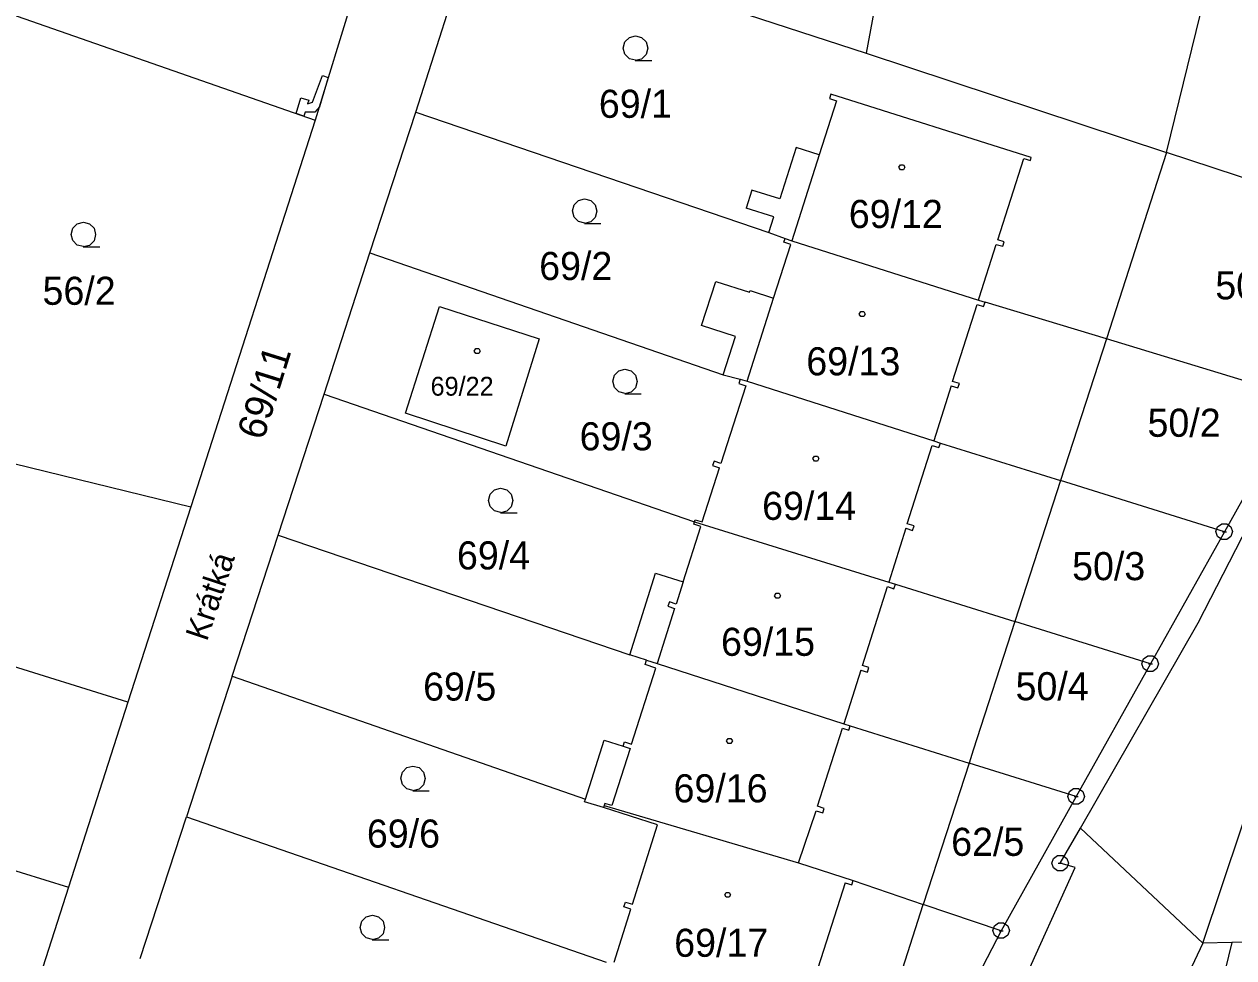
# Model space of a CAD drawing. Extents: x -759060 to -757386, y -1172273 to -1170948.
# Drawn here: x -757948.7 to -757875.5, y -1171352.6 to -1171296.1 of the extents above; entities that cross this region are included whole.
import ezdxf

# ---------------------------------------------------------------- set-up
doc = ezdxf.new("R2010")
doc.units = 0
for name, color, linetype in [('Vrstva 1', 7, 'Continuous'), ('Vrstva 12', 7, 'Continuous'), ('Vrstva 13', 7, 'Continuous'), ('Vrstva 2', 7, 'Continuous'), ('Vrstva 3', 7, 'Continuous'), ('Vrstva 4', 7, 'Continuous'), ('Vrstva 5', 7, 'Continuous'), ('Vrstva 7', 7, 'Continuous'), ('Vrstva 8', 7, 'Continuous')]:
    doc.layers.add(name, color=color, linetype=linetype)

msp = doc.modelspace()

# ---------------------------------------------------------------- linework, layer by layer
at = {"layer": 'Vrstva 1'}
for p, q in [((-757892.1, -1171267.11), (-757897.76, -1171297.84)), ((-757879.58, -1171303.85), (-757871.52, -1171270.95)), ((-757925.59, -1171283.81), (-757931.1, -1171301.9)), ((-757925.02, -1171301.41), (-757921.41, -1171290.12)), ((-757921.41, -1171290.12), (-757897.76, -1171297.84)), ((-757950, -1171295.3), (-757931.1, -1171301.9)), ((-757897.76, -1171297.84), (-757879.58, -1171303.85)), ((-757899.89, -1171300.32), (-757899.97, -1171300.59)), ((-757887.77, -1171304.16), (-757899.89, -1171300.32)), ((-757899.55, -1171300.73), (-757900.6, -1171303.99)), ((-757899.97, -1171300.59), (-757899.55, -1171300.73)), ((-757931.1, -1171301.9), (-757938.63, -1171325.3)), ((-757927.79, -1171309.92), (-757925.02, -1171301.41)), ((-757925.02, -1171301.41), (-757903.64, -1171308.7)), ((-757902, -1171303.54), (-757902.99, -1171306.66)), ((-757900.6, -1171303.99), (-757902, -1171303.54)), ((-757879.58, -1171303.85), (-757883.22, -1171315.14)), ((-757867.49, -1171307.82), (-757879.58, -1171303.85)), ((-757889.8, -1171309.14), (-757888.22, -1171304.21)), ((-757888.22, -1171304.21), (-757887.82, -1171304.34)), ((-757887.82, -1171304.34), (-757887.77, -1171304.16)), ((-757904.68, -1171306.12), (-757905.03, -1171307.22)), ((-757902.99, -1171306.66), (-757904.68, -1171306.12)), ((-757903.34, -1171307.75), (-757905.03, -1171307.22)), ((-757903.64, -1171308.7), (-757903.34, -1171307.75)), ((-757877.67, -1171332.33), (-757865.47, -1171308.48)), ((-757903.64, -1171308.7), (-757902.67, -1171309.05)), ((-757902.74, -1171309.28), (-757902.67, -1171309.05)), ((-757902.32, -1171309.41), (-757902.74, -1171309.28)), ((-757902.67, -1171309.05), (-757902.25, -1171309.19)), ((-757902.25, -1171309.19), (-757890.97, -1171312.79)), ((-757889.4, -1171309.26), (-757889.8, -1171309.14)), ((-757889.49, -1171309.53), (-757889.4, -1171309.26)), ((-757930.57, -1171318.47), (-757927.79, -1171309.92)), ((-757927.79, -1171309.92), (-757906.41, -1171317.31)), ((-757903.36, -1171312.66), (-757902.32, -1171309.41)), ((-757890.92, -1171312.65), (-757889.89, -1171309.41)), ((-757889.89, -1171309.41), (-757889.49, -1171309.53)), ((-757907.72, -1171314.32), (-757906.86, -1171311.66)), ((-757906.86, -1171311.66), (-757904.82, -1171312.31)), ((-757904.82, -1171312.31), (-757904.77, -1171312.2)), ((-757904.77, -1171312.2), (-757903.36, -1171312.66)), ((-757890.97, -1171312.79), (-757890.92, -1171312.65)), ((-757890.97, -1171312.79), (-757890.56, -1171312.92)), ((-757883.22, -1171315.14), (-757890.56, -1171312.92)), ((-757925.64, -1171319.63), (-757923.58, -1171313.18)), ((-757923.58, -1171313.18), (-757917.55, -1171315.13)), ((-757905.67, -1171314.98), (-757907.72, -1171314.32)), ((-757917.55, -1171315.13), (-757919.57, -1171321.62)), ((-757906.41, -1171317.31), (-757905.67, -1171314.98)), ((-757883.22, -1171315.14), (-757886, -1171323.71)), ((-757871.53, -1171318.68), (-757883.22, -1171315.14)), ((-757906.41, -1171317.31), (-757905.38, -1171317.57)), ((-757905.05, -1171317.97), (-757906.55, -1171322.67)), ((-757905.38, -1171317.57), (-757905.47, -1171317.84)), ((-757905.47, -1171317.84), (-757905.05, -1171317.97)), ((-757905.38, -1171317.57), (-757904.96, -1171317.7)), ((-757904.96, -1171317.7), (-757893.67, -1171321.31)), ((-757933.35, -1171327.02), (-757930.57, -1171318.47)), ((-757930.57, -1171318.47), (-757908.14, -1171326.21)), ((-757871.53, -1171318.68), (-757876.08, -1171326.81)), ((-757919.57, -1171321.62), (-757925.64, -1171319.63)), ((-757958.04, -1171320.56), (-757938.63, -1171325.3)), ((-757893.67, -1171321.31), (-757893.27, -1171321.44)), ((-757893.27, -1171321.44), (-757886, -1171323.71)), ((-757907.68, -1171326.21), (-757906.63, -1171322.94)), ((-757906.96, -1171322.54), (-757907.05, -1171322.8)), ((-757907.05, -1171322.8), (-757906.63, -1171322.94)), ((-757906.55, -1171322.67), (-757906.96, -1171322.54)), ((-757886, -1171323.71), (-757888.76, -1171332.25)), ((-757876.08, -1171326.81), (-757886, -1171323.71)), ((-757942.44, -1171337.12), (-757982.63, -1171324.67)), ((-757938.63, -1171325.3), (-757942.44, -1171337.12)), ((-757908.14, -1171326.21), (-757908.1, -1171326.08)), ((-757908.1, -1171326.08), (-757907.68, -1171326.21)), ((-757908.83, -1171329.84), (-757907.76, -1171326.49)), ((-757908.18, -1171326.35), (-757908.14, -1171326.21)), ((-757907.76, -1171326.49), (-757908.18, -1171326.35)), ((-757908.14, -1171326.21), (-757896.39, -1171329.86)), ((-757876.08, -1171326.81), (-757880.56, -1171334.81)), ((-757936.13, -1171335.56), (-757933.35, -1171327.02)), ((-757933.35, -1171327.02), (-757912.07, -1171334.26)), ((-757912.07, -1171334.26), (-757910.5, -1171329.31)), ((-757910.5, -1171329.31), (-757908.83, -1171329.84)), ((-757896.39, -1171329.86), (-757895.99, -1171329.99)), ((-757895.99, -1171329.99), (-757888.76, -1171332.25)), ((-757888.76, -1171332.25), (-757891.28, -1171340.03)), ((-757880.56, -1171334.81), (-757888.76, -1171332.25)), ((-757884.79, -1171344.75), (-757877.67, -1171332.33)), ((-757911.05, -1171334.59), (-757912.07, -1171334.26)), ((-757911.14, -1171334.85), (-757911.05, -1171334.59)), ((-757910.49, -1171335.06), (-757911.14, -1171334.85)), ((-757911.05, -1171334.59), (-757910.41, -1171334.79)), ((-757910.41, -1171334.79), (-757899.11, -1171338.44)), ((-757880.56, -1171334.81), (-757885.05, -1171342.84)), ((-757936.13, -1171335.56), (-757938.9, -1171344.07)), ((-757936.13, -1171335.56), (-757914.75, -1171342.99)), ((-757911.96, -1171339.66), (-757910.49, -1171335.06)), ((-757984.73, -1171336.38), (-757946.04, -1171348.32)), ((-757942.44, -1171337.12), (-757946.04, -1171348.32)), ((-757899.11, -1171338.44), (-757898.72, -1171338.56)), ((-757898.72, -1171338.56), (-757891.53, -1171340.81)), ((-757877.39, -1171351.72), (-757872.81, -1171338.04)), ((-757914.75, -1171342.99), (-757913.62, -1171339.43)), ((-757913.62, -1171339.43), (-757912.47, -1171339.79)), ((-757912.47, -1171339.79), (-757912.38, -1171339.53)), ((-757912.38, -1171339.53), (-757911.96, -1171339.66)), ((-757891.28, -1171340.03), (-757891.53, -1171340.81)), ((-757891.53, -1171340.81), (-757894.3, -1171349.37)), ((-757885.05, -1171342.84), (-757891.53, -1171340.81)), ((-757885.05, -1171342.84), (-757889.59, -1171350.96)), ((-757914.8, -1171343.15), (-757914.75, -1171342.99)), ((-757913.66, -1171343.51), (-757914.8, -1171343.15)), ((-757913.61, -1171343.39), (-757913.66, -1171343.51)), ((-757910.38, -1171344.56), (-757913.66, -1171343.51)), ((-757913.61, -1171343.39), (-757901.85, -1171346.86)), ((-757941.69, -1171352.64), (-757938.9, -1171344.07)), ((-757938.9, -1171344.07), (-757913.49, -1171352.86)), ((-757911.91, -1171349.36), (-757910.38, -1171344.56)), ((-757886.01, -1171346.88), (-757884.79, -1171344.75)), ((-757877.39, -1171351.72), (-757884.79, -1171344.75)), ((-757904.22, -1171389.43), (-757885.12, -1171347.13)), ((-757901.85, -1171346.86), (-757898.55, -1171347.93)), ((-757885.12, -1171347.13), (-757886.01, -1171346.88)), ((-757898.55, -1171347.93), (-757894.3, -1171349.37)), ((-757946.04, -1171348.32), (-757949.39, -1171358.74)), ((-757912.42, -1171349.51), (-757912.33, -1171349.23)), ((-757912, -1171349.65), (-757912.42, -1171349.51)), ((-757912.33, -1171349.23), (-757911.91, -1171349.36)), ((-757897.07, -1171357.94), (-757894.3, -1171349.37)), ((-757889.59, -1171350.96), (-757894.3, -1171349.37)), ((-757913.02, -1171352.86), (-757912, -1171349.65)), ((-757889.59, -1171350.96), (-757893.43, -1171358.41)), ((-757877.39, -1171351.72), (-757898.83, -1171397.44)), ((-757875.62, -1171351.68), (-757877.39, -1171351.72)), ((-757875.62, -1171351.68), (-757876.99, -1171357.1)), ((-757869.76, -1171351.53), (-757875.62, -1171351.68))]:
    msp.add_line(p, q, dxfattribs=at)
at = {"layer": 'Vrstva 12'}
for p, q in [((-757899.89, -1171300.32), (-757899.97, -1171300.59)), ((-757887.77, -1171304.16), (-757899.89, -1171300.32)), ((-757899.55, -1171300.73), (-757900.6, -1171303.99)), ((-757899.97, -1171300.59), (-757899.55, -1171300.73)), ((-757900.6, -1171303.99), (-757902.25, -1171309.19)), ((-757889.8, -1171309.14), (-757888.22, -1171304.21)), ((-757888.22, -1171304.21), (-757887.82, -1171304.34)), ((-757887.82, -1171304.34), (-757887.77, -1171304.16)), ((-757902.74, -1171309.28), (-757902.67, -1171309.05)), ((-757902.32, -1171309.41), (-757902.74, -1171309.28)), ((-757902.67, -1171309.05), (-757902.25, -1171309.19)), ((-757902.25, -1171309.19), (-757890.97, -1171312.79)), ((-757902.25, -1171309.19), (-757890.97, -1171312.79)), ((-757889.4, -1171309.26), (-757889.8, -1171309.14)), ((-757889.49, -1171309.53), (-757889.4, -1171309.26)), ((-757903.36, -1171312.66), (-757902.32, -1171309.41)), ((-757890.92, -1171312.65), (-757889.89, -1171309.41)), ((-757889.89, -1171309.41), (-757889.49, -1171309.53)), ((-757904.96, -1171317.7), (-757903.36, -1171312.66)), ((-757890.97, -1171312.79), (-757890.92, -1171312.65)), ((-757890.97, -1171312.79), (-757890.56, -1171312.92)), ((-757890.65, -1171313.18), (-757890.56, -1171312.92)), ((-757925.64, -1171319.63), (-757923.58, -1171313.18)), ((-757923.58, -1171313.18), (-757917.55, -1171315.13)), ((-757892.53, -1171317.71), (-757891.05, -1171313.06)), ((-757891.05, -1171313.06), (-757890.65, -1171313.18)), ((-757917.55, -1171315.13), (-757919.57, -1171321.62)), ((-757905.05, -1171317.97), (-757906.55, -1171322.67)), ((-757905.38, -1171317.57), (-757905.47, -1171317.84)), ((-757905.47, -1171317.84), (-757905.05, -1171317.97)), ((-757905.38, -1171317.57), (-757904.96, -1171317.7)), ((-757904.96, -1171317.7), (-757893.67, -1171321.31)), ((-757904.96, -1171317.7), (-757893.67, -1171321.31)), ((-757892.61, -1171317.97), (-757893.67, -1171321.31)), ((-757892.61, -1171317.97), (-757892.22, -1171318.1)), ((-757892.12, -1171317.84), (-757892.53, -1171317.71)), ((-757892.22, -1171318.1), (-757892.12, -1171317.84)), ((-757919.57, -1171321.62), (-757925.64, -1171319.63)), ((-757895.27, -1171326.33), (-757893.76, -1171321.58)), ((-757893.76, -1171321.58), (-757893.36, -1171321.71)), ((-757893.67, -1171321.31), (-757893.27, -1171321.44)), ((-757893.36, -1171321.71), (-757893.27, -1171321.44)), ((-757907.68, -1171326.21), (-757906.63, -1171322.94)), ((-757906.96, -1171322.54), (-757907.05, -1171322.8)), ((-757907.05, -1171322.8), (-757906.63, -1171322.94)), ((-757906.55, -1171322.67), (-757906.96, -1171322.54)), ((-757908.14, -1171326.21), (-757908.1, -1171326.08)), ((-757908.1, -1171326.08), (-757907.68, -1171326.21)), ((-757908.83, -1171329.84), (-757907.76, -1171326.49)), ((-757908.18, -1171326.35), (-757908.14, -1171326.21)), ((-757907.76, -1171326.49), (-757908.18, -1171326.35)), ((-757908.14, -1171326.21), (-757896.39, -1171329.86)), ((-757908.14, -1171326.21), (-757896.39, -1171329.86)), ((-757895.36, -1171326.6), (-757896.39, -1171329.86)), ((-757895.36, -1171326.6), (-757894.95, -1171326.73)), ((-757894.86, -1171326.46), (-757895.27, -1171326.33)), ((-757894.95, -1171326.73), (-757894.86, -1171326.46)), ((-757908.83, -1171329.84), (-757909.26, -1171331.19)), ((-757897.99, -1171334.9), (-757896.47, -1171330.13)), ((-757896.47, -1171330.13), (-757896.08, -1171330.26)), ((-757896.39, -1171329.86), (-757895.99, -1171329.99)), ((-757896.08, -1171330.26), (-757895.99, -1171329.99)), ((-757909.67, -1171331.05), (-757909.76, -1171331.32)), ((-757909.26, -1171331.19), (-757909.67, -1171331.05)), ((-757909.35, -1171331.45), (-757910.41, -1171334.79)), ((-757909.76, -1171331.32), (-757909.35, -1171331.45)), ((-757911.14, -1171334.85), (-757911.05, -1171334.59)), ((-757910.49, -1171335.06), (-757911.14, -1171334.85)), ((-757911.05, -1171334.59), (-757910.41, -1171334.79)), ((-757910.41, -1171334.79), (-757899.11, -1171338.44)), ((-757910.41, -1171334.79), (-757899.11, -1171338.44)), ((-757897.59, -1171335.03), (-757897.99, -1171334.9)), ((-757911.96, -1171339.66), (-757910.49, -1171335.06)), ((-757898.08, -1171335.18), (-757899.11, -1171338.44)), ((-757898.08, -1171335.18), (-757897.68, -1171335.3)), ((-757897.68, -1171335.3), (-757897.59, -1171335.03)), ((-757899.11, -1171338.44), (-757898.72, -1171338.56)), ((-757898.8, -1171338.83), (-757898.72, -1171338.56)), ((-757900.71, -1171343.43), (-757899.2, -1171338.7)), ((-757899.2, -1171338.7), (-757898.8, -1171338.83)), ((-757912.05, -1171339.93), (-757913.15, -1171343.39)), ((-757912.47, -1171339.79), (-757912.38, -1171339.53)), ((-757912.47, -1171339.79), (-757912.05, -1171339.93)), ((-757912.38, -1171339.53), (-757911.96, -1171339.66)), ((-757913.61, -1171343.39), (-757913.66, -1171343.51)), ((-757910.38, -1171344.56), (-757913.66, -1171343.51)), ((-757913.57, -1171343.26), (-757913.61, -1171343.39)), ((-757913.61, -1171343.39), (-757901.85, -1171346.86)), ((-757913.61, -1171343.39), (-757901.85, -1171346.86)), ((-757913.15, -1171343.39), (-757913.57, -1171343.26)), ((-757900.3, -1171343.56), (-757900.71, -1171343.43)), ((-757900.39, -1171343.83), (-757900.3, -1171343.56)), ((-757901.85, -1171346.86), (-757900.79, -1171343.7)), ((-757900.79, -1171343.7), (-757900.39, -1171343.83)), ((-757911.91, -1171349.36), (-757910.38, -1171344.56)), ((-757901.85, -1171346.86), (-757898.55, -1171347.93)), ((-757899.03, -1171348.06), (-757901.72, -1171356.43)), ((-757899.03, -1171348.06), (-757898.63, -1171348.19)), ((-757898.63, -1171348.19), (-757898.55, -1171347.93)), ((-757912.42, -1171349.51), (-757912.33, -1171349.23)), ((-757912, -1171349.65), (-757912.42, -1171349.51)), ((-757912.33, -1171349.23), (-757911.91, -1171349.36)), ((-757913.02, -1171352.86), (-757912, -1171349.65))]:
    msp.add_line(p, q, dxfattribs=at)
at = {"layer": 'Vrstva 13'}
for p, q in [((-757931.27, -1171300.8), (-757930.66, -1171299.18)), ((-757930.31, -1171299.31), (-757930.85, -1171301.08)), ((-757930.66, -1171299.18), (-757930.31, -1171299.31)), ((-757932.26, -1171301.49), (-757931.97, -1171300.54)), ((-757931.97, -1171300.54), (-757931.49, -1171300.68)), ((-757931.49, -1171300.68), (-757931.56, -1171300.91)), ((-757931.56, -1171300.91), (-757931.27, -1171300.8)), ((-757930.85, -1171301.08), (-757931.12, -1171301.41)), ((-757931.79, -1171301.66), (-757932.26, -1171301.49)), ((-757931.72, -1171301.41), (-757931.79, -1171301.66)), ((-757931.12, -1171301.41), (-757931.72, -1171301.41))]:
    msp.add_line(p, q, dxfattribs=at)
at = {"layer": 'Vrstva 3'}
for points in [[(-757911.71, -1171298.27), (-757912.09, -1171298.17), (-757912.36, -1171297.9), (-757912.46, -1171297.53), (-757912.36, -1171297.16), (-757912.09, -1171296.89), (-757911.72, -1171296.79), (-757911.35, -1171296.89), (-757911.08, -1171297.16), (-757910.98, -1171297.54), (-757911.08, -1171297.92), (-757911.35, -1171298.19), (-757911.73, -1171298.29), (-757910.73, -1171298.29)], [(-757914.79, -1171308.13), (-757915.17, -1171308.03), (-757915.44, -1171307.76), (-757915.54, -1171307.39), (-757915.44, -1171307.02), (-757915.17, -1171306.75), (-757914.8, -1171306.65), (-757914.43, -1171306.75), (-757914.16, -1171307.02), (-757914.06, -1171307.4), (-757914.16, -1171307.78), (-757914.43, -1171308.05), (-757914.81, -1171308.15), (-757913.81, -1171308.15)], [(-757945.12, -1171309.55), (-757945.5, -1171309.45), (-757945.77, -1171309.18), (-757945.87, -1171308.81), (-757945.77, -1171308.44), (-757945.5, -1171308.17), (-757945.13, -1171308.07), (-757944.76, -1171308.17), (-757944.49, -1171308.44), (-757944.39, -1171308.82), (-757944.49, -1171309.2), (-757944.76, -1171309.47), (-757945.14, -1171309.57), (-757944.14, -1171309.57)], [(-757912.35, -1171318.44), (-757912.73, -1171318.34), (-757913, -1171318.07), (-757913.1, -1171317.7), (-757913, -1171317.33), (-757912.73, -1171317.06), (-757912.36, -1171316.96), (-757911.99, -1171317.06), (-757911.72, -1171317.33), (-757911.62, -1171317.71), (-757911.72, -1171318.09), (-757911.99, -1171318.36), (-757912.37, -1171318.46), (-757911.37, -1171318.46)], [(-757919.87, -1171325.65), (-757920.25, -1171325.55), (-757920.52, -1171325.28), (-757920.62, -1171324.91), (-757920.52, -1171324.54), (-757920.25, -1171324.27), (-757919.88, -1171324.17), (-757919.51, -1171324.27), (-757919.24, -1171324.54), (-757919.14, -1171324.92), (-757919.24, -1171325.3), (-757919.51, -1171325.57), (-757919.89, -1171325.67), (-757918.89, -1171325.67)], [(-757925.18, -1171342.47), (-757925.56, -1171342.37), (-757925.83, -1171342.1), (-757925.93, -1171341.73), (-757925.83, -1171341.36), (-757925.56, -1171341.09), (-757925.19, -1171340.99), (-757924.82, -1171341.09), (-757924.55, -1171341.36), (-757924.45, -1171341.74), (-757924.55, -1171342.12), (-757924.82, -1171342.39), (-757925.2, -1171342.49), (-757924.2, -1171342.49)], [(-757927.63, -1171351.5), (-757928.01, -1171351.4), (-757928.28, -1171351.13), (-757928.38, -1171350.76), (-757928.28, -1171350.39), (-757928.01, -1171350.12), (-757927.64, -1171350.02), (-757927.27, -1171350.12), (-757927, -1171350.39), (-757926.9, -1171350.77), (-757927, -1171351.15), (-757927.27, -1171351.42), (-757927.65, -1171351.52), (-757926.65, -1171351.52)]]:
    msp.add_lwpolyline(points, dxfattribs=at)
at = {"layer": 'Vrstva 4'}
for p, q in [((-757900.6, -1171303.99), (-757902.25, -1171309.19)), ((-757904.96, -1171317.7), (-757903.36, -1171312.66)), ((-757890.65, -1171313.18), (-757890.56, -1171312.92)), ((-757892.53, -1171317.71), (-757891.05, -1171313.06)), ((-757891.05, -1171313.06), (-757890.65, -1171313.18)), ((-757892.61, -1171317.97), (-757893.67, -1171321.31)), ((-757892.61, -1171317.97), (-757892.22, -1171318.1)), ((-757892.12, -1171317.84), (-757892.53, -1171317.71)), ((-757892.22, -1171318.1), (-757892.12, -1171317.84)), ((-757895.27, -1171326.33), (-757893.76, -1171321.58)), ((-757893.76, -1171321.58), (-757893.36, -1171321.71)), ((-757893.36, -1171321.71), (-757893.27, -1171321.44)), ((-757895.36, -1171326.6), (-757896.39, -1171329.86)), ((-757895.36, -1171326.6), (-757894.95, -1171326.73)), ((-757894.86, -1171326.46), (-757895.27, -1171326.33)), ((-757894.95, -1171326.73), (-757894.86, -1171326.46)), ((-757908.83, -1171329.84), (-757909.26, -1171331.19)), ((-757897.99, -1171334.9), (-757896.47, -1171330.13)), ((-757896.47, -1171330.13), (-757896.08, -1171330.26)), ((-757896.08, -1171330.26), (-757895.99, -1171329.99)), ((-757909.67, -1171331.05), (-757909.76, -1171331.32)), ((-757909.26, -1171331.19), (-757909.67, -1171331.05)), ((-757909.35, -1171331.45), (-757910.41, -1171334.79)), ((-757909.76, -1171331.32), (-757909.35, -1171331.45)), ((-757897.59, -1171335.03), (-757897.99, -1171334.9)), ((-757898.08, -1171335.18), (-757899.11, -1171338.44)), ((-757898.08, -1171335.18), (-757897.68, -1171335.3)), ((-757897.68, -1171335.3), (-757897.59, -1171335.03)), ((-757898.8, -1171338.83), (-757898.72, -1171338.56)), ((-757900.71, -1171343.43), (-757899.2, -1171338.7)), ((-757899.2, -1171338.7), (-757898.8, -1171338.83)), ((-757912.05, -1171339.93), (-757913.15, -1171343.39)), ((-757912.47, -1171339.79), (-757912.05, -1171339.93)), ((-757913.57, -1171343.26), (-757913.61, -1171343.39)), ((-757913.15, -1171343.39), (-757913.57, -1171343.26)), ((-757900.3, -1171343.56), (-757900.71, -1171343.43)), ((-757900.39, -1171343.83), (-757900.3, -1171343.56)), ((-757901.85, -1171346.86), (-757900.79, -1171343.7)), ((-757900.79, -1171343.7), (-757900.39, -1171343.83)), ((-757899.03, -1171348.06), (-757901.72, -1171356.43)), ((-757899.03, -1171348.06), (-757898.63, -1171348.19)), ((-757898.63, -1171348.19), (-757898.55, -1171347.93))]:
    msp.add_line(p, q, dxfattribs=at)
at = {"layer": 'Vrstva 5'}
for points in [[(-757895.51, -1171304.59), (-757895.42, -1171304.74), (-757895.51, -1171304.89), (-757895.69, -1171304.89), (-757895.78, -1171304.74), (-757895.69, -1171304.59)], [(-757897.91, -1171313.48), (-757897.82, -1171313.63), (-757897.91, -1171313.78), (-757898.09, -1171313.78), (-757898.18, -1171313.63), (-757898.09, -1171313.48)], [(-757921.21, -1171315.72), (-757921.12, -1171315.87), (-757921.21, -1171316.02), (-757921.39, -1171316.02), (-757921.48, -1171315.87), (-757921.39, -1171315.72)], [(-757900.71, -1171322.23), (-757900.62, -1171322.38), (-757900.71, -1171322.53), (-757900.89, -1171322.53), (-757900.98, -1171322.38), (-757900.89, -1171322.23)], [(-757903.03, -1171330.53), (-757902.94, -1171330.68), (-757903.03, -1171330.83), (-757903.21, -1171330.83), (-757903.3, -1171330.68), (-757903.21, -1171330.53)], [(-757905.94, -1171339.32), (-757905.85, -1171339.47), (-757905.94, -1171339.62), (-757906.12, -1171339.62), (-757906.21, -1171339.47), (-757906.12, -1171339.32)], [(-757906.05, -1171348.64), (-757905.96, -1171348.79), (-757906.05, -1171348.94), (-757906.23, -1171348.94), (-757906.32, -1171348.79), (-757906.23, -1171348.64)]]:
    msp.add_lwpolyline(points, close=True, dxfattribs=at)
at = {"layer": 'Vrstva 8'}
for p, q in [((-757876.2, -1171326.81), (-757875.96, -1171326.81)), ((-757880.68, -1171334.81), (-757880.44, -1171334.81)), ((-757885.17, -1171342.84), (-757884.93, -1171342.84)), ((-757886.13, -1171346.88), (-757885.89, -1171346.88)), ((-757889.71, -1171350.96), (-757889.47, -1171350.96))]:
    msp.add_line(p, q, dxfattribs=at)
for points in [[(-757875.93, -1171326.33), (-757875.68, -1171326.51), (-757875.58, -1171326.8), (-757875.68, -1171327.09), (-757875.93, -1171327.27), (-757876.24, -1171327.27), (-757876.49, -1171327.09), (-757876.59, -1171326.8), (-757876.49, -1171326.51), (-757876.24, -1171326.33)], [(-757880.41, -1171334.33), (-757880.16, -1171334.51), (-757880.06, -1171334.8), (-757880.16, -1171335.09), (-757880.41, -1171335.27), (-757880.72, -1171335.27), (-757880.97, -1171335.09), (-757881.07, -1171334.8), (-757880.97, -1171334.51), (-757880.72, -1171334.33)], [(-757884.9, -1171342.36), (-757884.65, -1171342.54), (-757884.55, -1171342.83), (-757884.65, -1171343.12), (-757884.9, -1171343.3), (-757885.21, -1171343.3), (-757885.46, -1171343.12), (-757885.56, -1171342.83), (-757885.46, -1171342.54), (-757885.21, -1171342.36)], [(-757885.86, -1171346.4), (-757885.61, -1171346.58), (-757885.51, -1171346.87), (-757885.61, -1171347.16), (-757885.86, -1171347.34), (-757886.17, -1171347.34), (-757886.42, -1171347.16), (-757886.52, -1171346.87), (-757886.42, -1171346.58), (-757886.17, -1171346.4)], [(-757889.44, -1171350.48), (-757889.19, -1171350.66), (-757889.09, -1171350.95), (-757889.19, -1171351.24), (-757889.44, -1171351.42), (-757889.75, -1171351.42), (-757890, -1171351.24), (-757890.1, -1171350.95), (-757890, -1171350.66), (-757889.75, -1171350.48)]]:
    msp.add_lwpolyline(points, close=True, dxfattribs=at)

# ---------------------------------------------------------------- texts
at = {"layer": 'Vrstva 2'}
for s, height, p in [('69/1', 1.7, (-757913.936, -1171301.75)), ('69/12', 1.7, (-757898.809, -1171308.42)), ('69/2', 1.7, (-757917.547, -1171311.57)), ('56/2', 1.7, (-757947.604, -1171313.07)), ('50/1', 1.7, (-757876.629, -1171312.74)), ('69/13', 1.7, (-757901.382, -1171317.34)), ('69/22', 1.14, (-757924.121, -1171318.57)), ('50/2', 1.7, (-757880.731, -1171321.06)), ('69/3', 1.7, (-757915.101, -1171321.88)), ('69/14', 1.7, (-757904.055, -1171326.09)), ('69/4', 1.7, (-757922.524, -1171329.09)), ('50/3', 1.7, (-757885.295, -1171329.74)), ('69/15', 1.7, (-757906.542, -1171334.32)), ('69/5', 1.7, (-757924.571, -1171337.03)), ('50/4', 1.7, (-757888.717, -1171337.01)), ('69/16', 1.7, (-757909.415, -1171343.19)), ('69/6', 1.7, (-757927.974, -1171345.93)), ('62/5', 1.7, (-757892.614, -1171346.43)), ('69/17', 1.7, (-757909.375, -1171352.54))]:
    msp.add_text(s, height=height, dxfattribs=at).set_placement(p)
msp.add_text('69/11', height=1.7, rotation=72.59375, dxfattribs=at).set_placement((-757934.239, -1171321.332))
at = {"layer": 'Vrstva 7'}
msp.add_text('Krátká', height=1.4, rotation=71.61973, dxfattribs=at).set_placement((-757937.657, -1171333.491))

doc.saveas('drawing.dxf')
